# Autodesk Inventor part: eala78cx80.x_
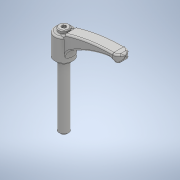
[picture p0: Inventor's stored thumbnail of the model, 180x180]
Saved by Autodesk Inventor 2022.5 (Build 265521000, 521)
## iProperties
Created: 2018-05
Part Number: eala78cx80.x_
Material: 一般
Document SubType Name: Modeling
Designer: imaocorp
Density: 1 g/cm^3
Appearance: 既定
Sending System: SOLIDWORKS 2016-2016286
MC: AMD64
MC_MODEL: AMD64 Family 21 Model 2 Stepping 0, AuthenticAMD
OS: Windows_NT
FRU: Parasolid Version 28.0, build 224,  7-29-2016
FORMAT: text
GUISE: transmit
KEY: eala78cx80
FILE: eala78cx80.x_t
DATE: Fri May 18 11:32:41 2018
Author: imaocorp
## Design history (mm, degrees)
feature "Base1"
node "ソリッド1"
